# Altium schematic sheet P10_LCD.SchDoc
size A1
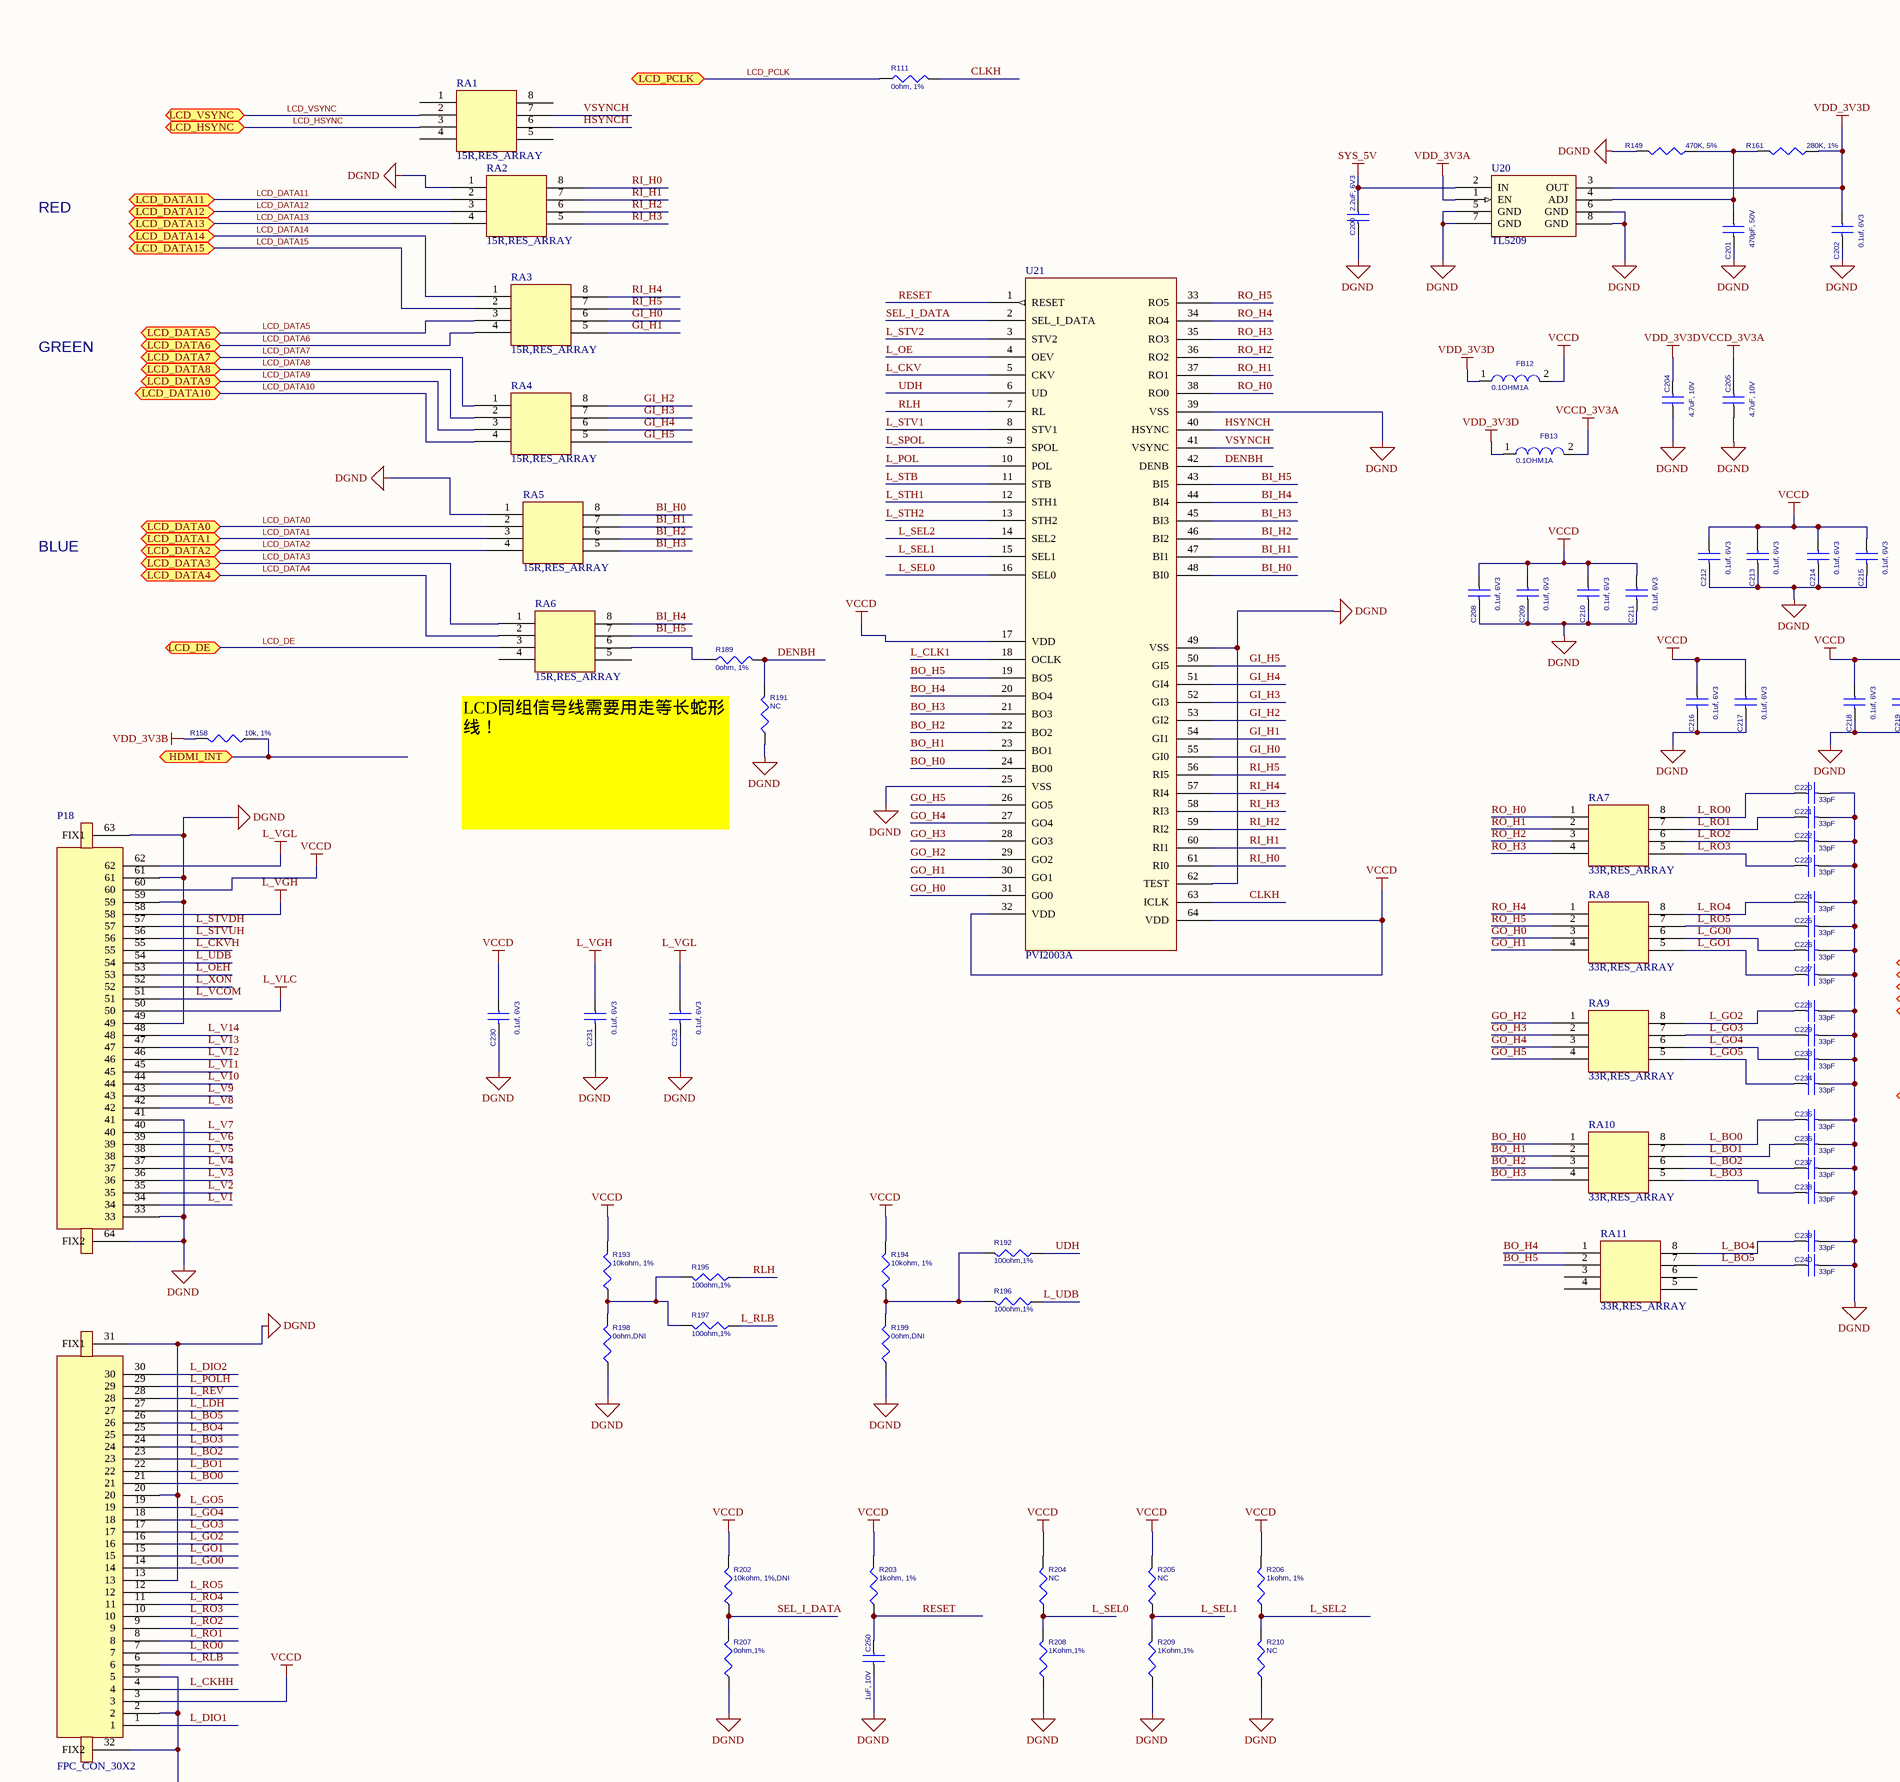
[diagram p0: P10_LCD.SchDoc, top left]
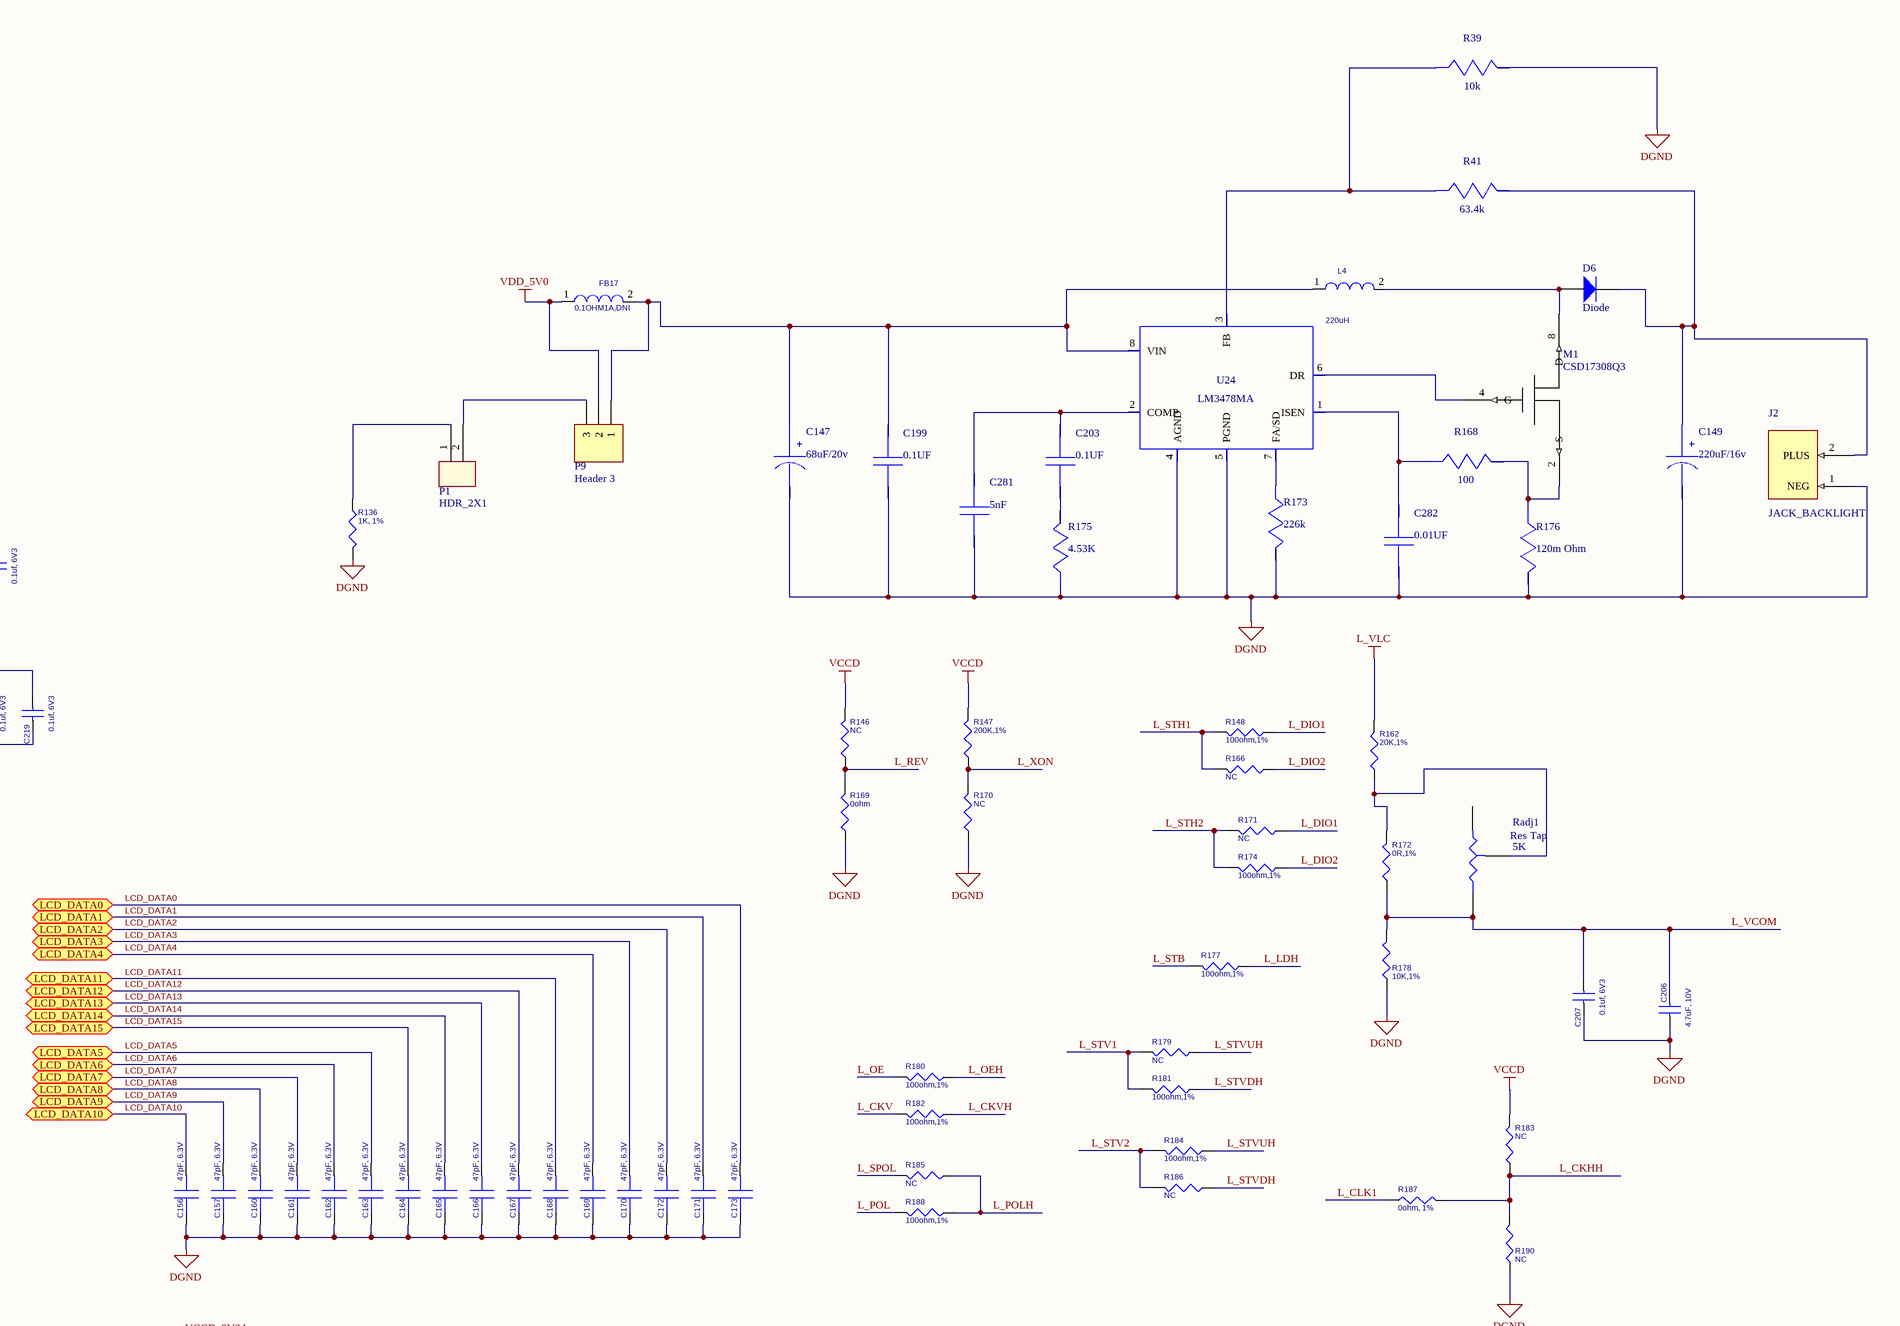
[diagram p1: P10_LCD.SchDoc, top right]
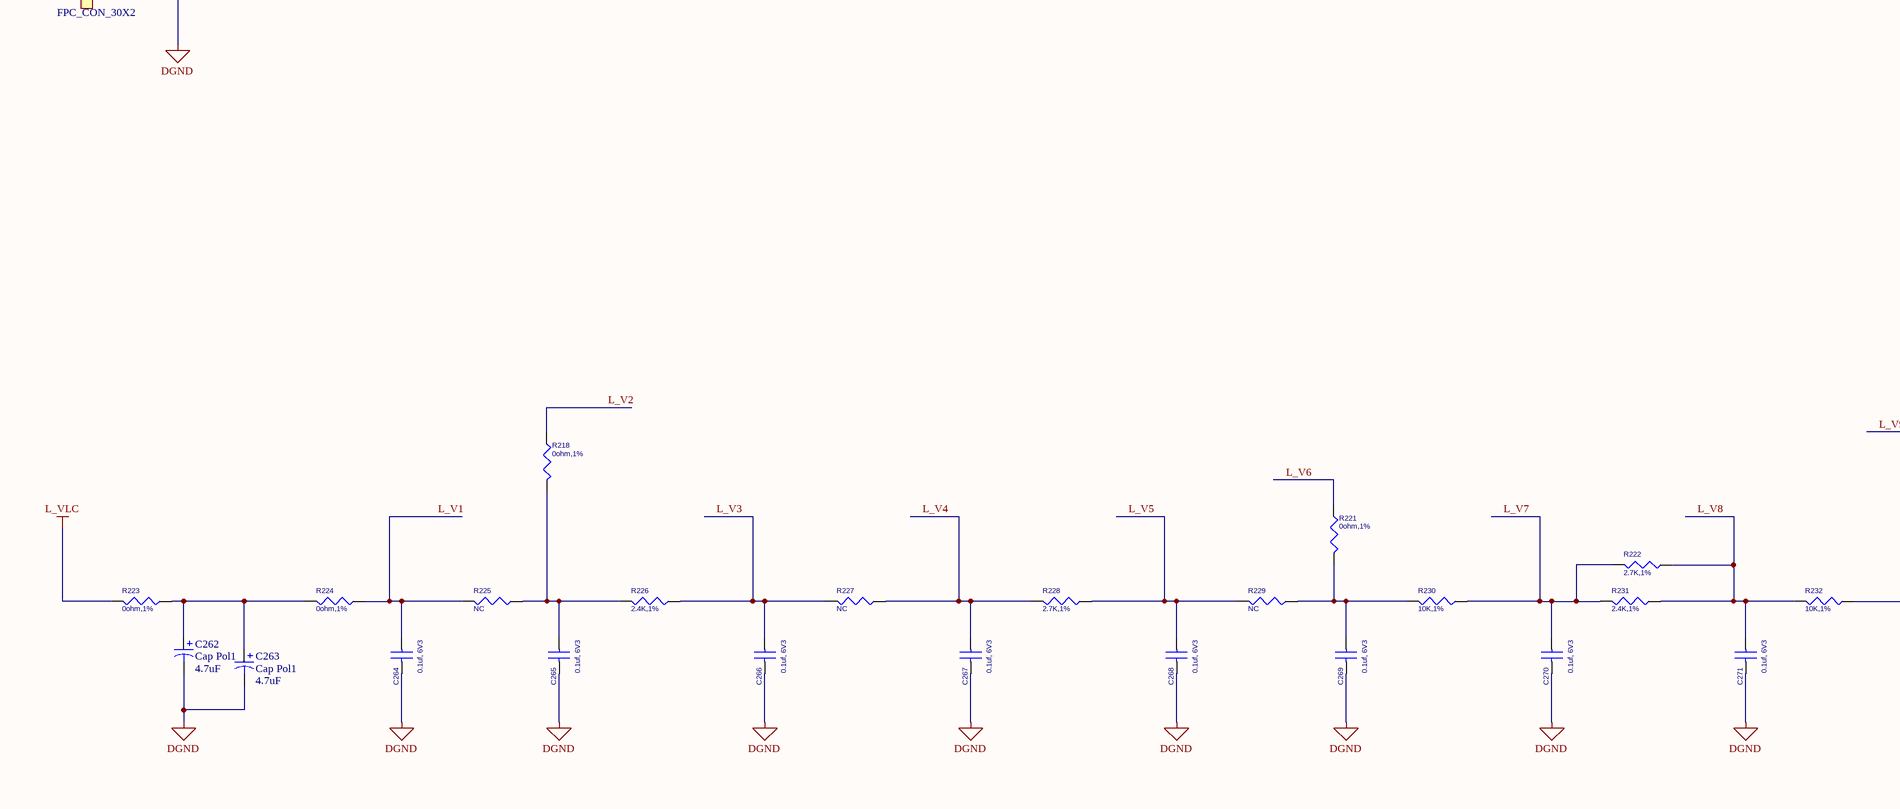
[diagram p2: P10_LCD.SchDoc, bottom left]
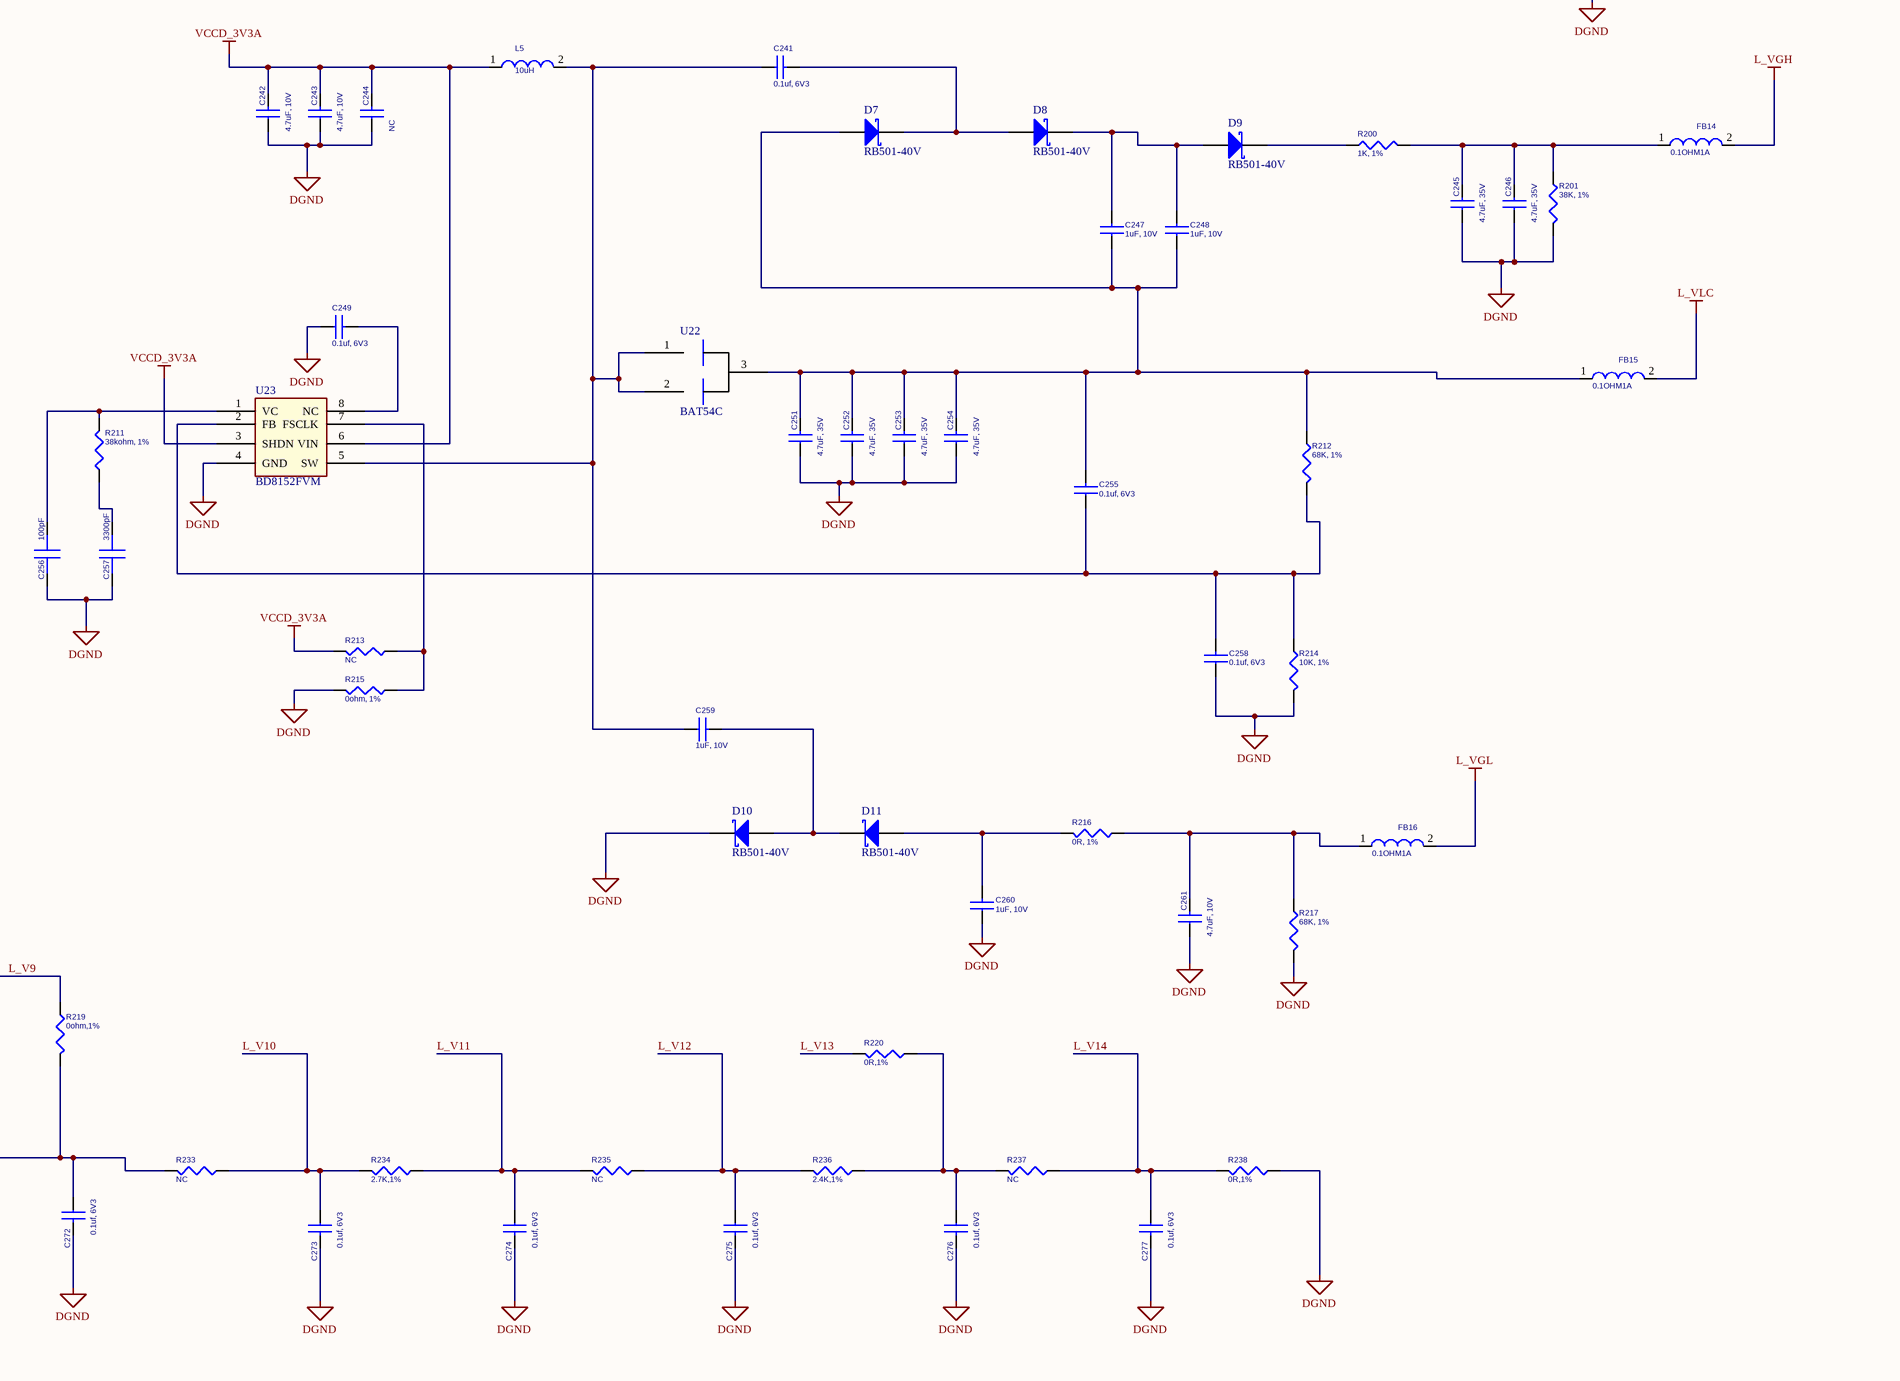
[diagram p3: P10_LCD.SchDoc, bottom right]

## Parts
C147  value 68uF/20v  [7343T]  (hidden comment: EEE-FK1A220R)
C149  value 220uF/16v  [7343T]  (hidden comment: 16SVP180M)
C156  47pF, 6.3V  [402]
C157  47pF, 6.3V  [402]
C160  47pF, 6.3V  [402]
C161  47pF, 6.3V  [402]
C162  47pF, 6.3V  [402]
C163  47pF, 6.3V  [402]
C164  47pF, 6.3V  [402]
C165  47pF, 6.3V  [402]
C166  47pF, 6.3V  [402]
C167  47pF, 6.3V  [402]
C168  47pF, 6.3V  [402]
C169  47pF, 6.3V  [402]
C170  47pF, 6.3V  [402]
C171  47pF, 6.3V  [402]
C172  47pF, 6.3V  [402]
C173  47pF, 6.3V  [402]
C199  value 0.1UF  [0805]  (hidden comment: C1005X5R0J104K)
C200  2.2uF, 6V3  [0805]
C201  470pF, 50V  [402]
C202  0.1uf, 6V3  [402]
C203  value 0.1UF  [0805]  (hidden comment: GRM216R71H103KA01D)
C204  4.7uF, 10V  [805]
C205  4.7uF, 10V  [805]
C206  4.7uF, 10V  [805]
C207  0.1uf, 6V3  [402]
C208  0.1uf, 6V3  [402]
C209  0.1uf, 6V3  [402]
C210  0.1uf, 6V3  [402]
C211  0.1uf, 6V3  [402]
C212  0.1uf, 6V3  [402]
C213  0.1uf, 6V3  [402]
C214  0.1uf, 6V3  [402]
C215  0.1uf, 6V3  [402]
C216  0.1uf, 6V3  [402]
C217  0.1uf, 6V3  [402]
C218  0.1uf, 6V3  [402]
C219  0.1uf, 6V3  [402]
C220  33pF  [402]
C221  33pF  [402]
C222  33pF  [402]
C223  33pF  [402]
C224  33pF  [402]
C225  33pF  [402]
C226  33pF  [402]
C227  33pF  [402]
C228  33pF  [402]
C229  33pF  [402]
C230  0.1uf, 6V3  [402]
C231  0.1uf, 6V3  [402]
C232  0.1uf, 6V3  [402]
C233  33pF  [402]
C234  33pF  [402]
C235  33pF  [402]
C236  33pF  [402]
C237  33pF  [402]
C238  33pF  [402]
C239  33pF  [402]
C240  33pF  [402]
C241  0.1uf, 6V3  [402]
C242  4.7uF, 10V  [805]
C243  4.7uF, 10V  [805]
C244  NC  [805]
C245  4.7uF, 35V  [1210]
C246  4.7uF, 35V  [1210]
C247  1uF, 10V  [0805]
C248  1uF, 10V  [0805]
C249  0.1uf, 6V3  [402]
C250  1uF, 10V  [0805]
C251  4.7uF, 35V  [1210]
C252  4.7uF, 35V  [1210]
C253  4.7uF, 35V  [1210]
C254  4.7uF, 35V  [1210]
C255  0.1uf, 6V3  [402]
C256  100pF  [402]
C257  3300pF  [C0603]
C258  0.1uf, 6V3  [402]
C259  1uF, 10V  [0805]
C260  1uF, 10V  [0805]
C261  4.7uF, 10V  [805]
C262  Cap Pol1  value 4.7uF  [6032/case C]
C263  Cap Pol1  value 4.7uF  [6032/case C]
C264  0.1uf, 6V3  [402]
C265  0.1uf, 6V3  [402]
C266  0.1uf, 6V3  [402]
C267  0.1uf, 6V3  [402]
C268  0.1uf, 6V3  [402]
C269  0.1uf, 6V3  [402]
C270  0.1uf, 6V3  [402]
C271  0.1uf, 6V3  [402]
C272  0.1uf, 6V3  [402]
C273  0.1uf, 6V3  [402]
C274  0.1uf, 6V3  [402]
C275  0.1uf, 6V3  [402]
C276  0.1uf, 6V3  [402]
C277  0.1uf, 6V3  [402]
C281  value 5nF  [0805]  (hidden comment: CC0805KRX7R9BB561)
C282  value 0.01UF  [0805]  (hidden comment: GRM216R71H103KA01D)
D6  Diode  [DSO-C2/X3.3]
D7  RB501-40V  [DSO-C2/X2.3]
D8  RB501-40V  [DSO-C2/X2.3]
D9  RB501-40V  [DSO-C2/X2.3]
D10  RB501-40V  [DSO-C2/X2.3]
D11  RB501-40V  [DSO-C2/X2.3]
FB12  0.1OHM1A  [SM-7351-IND-0805]
FB13  0.1OHM1A  [SM-7351-IND-0805]
FB14  0.1OHM1A  [SM-7351-IND-0805]
FB15  0.1OHM1A  [SM-7351-IND-0805]
FB16  0.1OHM1A  [SM-7351-IND-0805]
FB17  0.1OHM1A,DNI  [SM-7351-IND-0805]
J2  JACK_BACKLIGHT  [JACK_BACKLIGHT]
L4  220uH  [L330]
L5  10uH  [2520]
M1  CSD17308Q3  [MOSFET_Q3]
P1  HDR_2X1  [HDR_2X1]
P9  Header 3  [HDR1X3]
P18  FPC_CON_30X2  [FPC_CON_30X2]
R39  value 10k  [R0603]  (hidden comment: CRCW04021K00FKED)
R41  value 63.4k  [R0603]  (hidden comment: CRCW04027K68FKED)
R111  0ohm, 1%  [R0805]
R136  1K, 1%  [R0603]
R146  NC  [R0805]
R147  200K,1%  [R0805]
R148  100ohm,1%  [R0603]
R149  470K, 5%  [R0402]
R158  10k, 1%  [R0402]
R161  280K, 1%  [R0402]
R162  20K,1%  [R0805]
R166  NC  [R0603]
R168  value 100  [R0603]  (hidden comment: CRCW0402100RFKED)
R169  0ohm  [R0805]
R170  NC  [R0805]
R171  NC  [R0603]
R172  0R,1%  [R0805]
R173  value 226k  [R0603]  (hidden comment: CRCW040228K7FKED)
R174  100ohm,1%  [R0603]
R175  value 4.53K  [R0603]  (hidden comment: CRCW040211K0FKED)
R176  value 120m Ohm  [R2010]  (hidden comment: CSRN2010FK60L0)
R177  100ohm,1%  [R0603]
R178  10K,1%  [R0805]
R179  NC  [R0603]
R180  100ohm,1%  [R0603]
R181  100ohm,1%  [R0603]
R182  100ohm,1%  [R0603]
R183  NC  [R0805]
R184  100ohm,1%  [R0603]
R185  NC  [R0603]
R186  NC  [R0603]
R187  0ohm, 1%  [R0805]
R188  100ohm,1%  [R0603]
R189  0ohm, 1%  [R0805]
R190  NC  [R0805]
R191  NC  [R0805]
R192  100ohm,1%  [R0603]
R193  10kohm, 1%  [R0805]
R194  10kohm, 1%  [R0805]
R195  100ohm,1%  [R0603]
R196  100ohm,1%  [R0603]
R197  100ohm,1%  [R0603]
R198  0ohm,DNI  [R0805]
R199  0ohm,DNI  [R0805]
R200  1K, 1%  [R0805]
R201  38K, 1%  [R0805]
R202  10kohm, 1%,DNI  [R0805]
R203  1kohm, 1%  [R0805]
R204  NC  [R0805]
R205  NC  [R0805]
R206  1kohm, 1%  [R0805]
R207  0ohm,1%  [R0805]
R208  1Kohm,1%  [R0805]
R209  1Kohm,1%  [R0805]
R210  NC  [R0805]
R211  38kohm, 1%  [R0805]
R212  68K, 1%  [R0805]
R213  NC  [R0805]
R214  10K, 1%  [R0805]
R215  0ohm, 1%  [R0805]
R216  0R, 1%  [R0805]
R217  68K, 1%  [R0805]
R218  0ohm,1%  [R0805]
R219  0ohm,1%  [R0805]
R220  0R,1%  [R0805]
R221  0ohm,1%  [R0805]
R222  2.7K,1%  [R0805]
R223  0ohm,1%  [R0805]
R224  0ohm,1%  [R0805]
R225  NC  [R0805]
R226  2.4K,1%  [R0805]
R227  NC  [R0805]
R228  2.7K,1%  [R0805]
R229  NC  [R0805]
R230  10K,1%  [R0805]
R231  2.4K,1%  [R0805]
R232  10K,1%  [R0805]
R233  NC  [R0805]
R234  2.7K,1%  [R0805]
R235  NC  [R0805]
R236  2.4K,1%  [R0805]
R237  NC  [R0805]
R238  0R,1%  [R0805]
RA1  15R,RES_ARRAY  [R8_0603]
RA2  15R,RES_ARRAY  [R8_0603]
RA3  15R,RES_ARRAY  [R8_0603]
RA4  15R,RES_ARRAY  [R8_0603]
RA5  15R,RES_ARRAY  [R8_0603]
RA6  15R,RES_ARRAY  [R8_0603]
RA7  33R,RES_ARRAY  [R8_0603]
RA8  33R,RES_ARRAY  [R8_0603]
RA9  33R,RES_ARRAY  [R8_0603]
RA10  33R,RES_ARRAY  [R8_0603]
RA11  33R,RES_ARRAY  [R8_0603]
Radj1  Res Tap  value 5K  [RADJ]
U20  TL5209  [SO8-25X75/TL5209DR/8-SOIC]
U21  PVI2003A  [TQFP13-64 STD/PVI2003A]
U22  BAT54C  [SOT-23/BAT54C]
U23  BD8152FVM  [MSOP8/BD8152FVM]
U24  LM3478MA  [SOP8_LM3478]

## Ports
HDMI_INT, LCD_DATA0, LCD_DATA1, LCD_DATA2, LCD_DATA3, LCD_DATA4, LCD_DATA5, LCD_DATA6, LCD_DATA7, LCD_DATA8, LCD_DATA9, LCD_DATA10, LCD_DATA11, LCD_DATA12, LCD_DATA13, LCD_DATA14, LCD_DATA15, LCD_DE, LCD_HSYNC, LCD_PCLK, LCD_VSYNC

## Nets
DGND: C147.2(-) C149.2(-) C156.2 C157.2 C160.2 C161.2 C162.2 C163.2 C164.2 C165.2 C166.2 C167.2 C168.2 C169.2 C170.2 C171.2 C172.2 C173.2 C199.2 C200.2 C201.2 C202.2 C204.1 C205.1 C206.1 C207.2 C208.2 C209.2 C210.2 C211.2 C212.2 C213.2 C214.2 C215.2 C216.2 C217.2 C218.2 C219.2 C220.2 C221.2 C222.2 C223.2 C224.2 C225.2 C226.2 C227.2 C228.2 C229.2 C230.2 C231.2 C232.2 C233.2 C234.2 C235.2 C236.2 C237.2 C238.2 C239.2 C240.2 C242.1 C243.1 C244.1 C245.1 C246.1 C249.1 C250.2 C251.1 C252.1 C253.1 C254.1 C256.2 C257.2 C258.1 C260.1 C261.1 C262.2 C263.2 C264.2 C265.2 C266.2 C267.2 C268.2 C269.2 C270.2 C271.2 C272.2 C273.2 C274.2 C275.2 C276.2 C277.2 C281.2 C282.2 D10.2(K) J2.1(NEG) P18.2 P18.5 P18.13 P18.20 P18.31(FIX1) P18.32(FIX2) P18.33 P18.41 P18.49 P18.59 P18.61 P18.63(FIX1) P18.64(FIX2) R39.1 R136.2 R149.2 R169.2(P2) R170.2(P2) R173.1 R175.2 R176.1 R178.2(P2) R190.2(P2) R191.2(P2) R198.2(P2) R199.2(P2) R201.1(P1) R207.2(P2) R208.2(P2) R209.2(P2) R210.2(P2) R214.1(P1) R215.1(P1) R217.1(P1) R238.2(P2) RA2.1 RA5.1 U20.5(GND) U20.6(GND) U20.7(GND) U20.8(GND) U21.25(VSS) U21.39(VSS) U21.49(VSS) U21.62(TEST) U23.4(GND) U24.4(AGND) U24.5(PGND)
L_VGH: C231.1 FB14.2 P18.58
L_VGL: C232.1 FB16.2 P18.62
L_VLC: FB15.2 P18.50 R162.1(P1) R223.1(P1)
SYS_5V: C200.1 U20.2(IN)
VCCD: C208.1 C209.1 C210.1 C211.1 C212.1 C213.1 C214.1 C215.1 C216.1 C217.1 C218.1 C219.1 C230.1 FB12.2 P18.3 P18.60 R146.1(P1) R147.1(P1) R183.1(P1) R193.1(P1) R194.1(P1) R202.1(P1) R203.1(P1) R204.1(P1) R205.1(P1) R206.1(P1) U21.17(VDD) U21.32(VDD) U21.64(VDD)
VCCD_3V3A: C205.2 C242.2 C243.2 C244.2 FB13.2 L5.1 R213.1(P1) U23.3(SHDN) U23.6(VIN)
VDD_3V3A: U20.1(EN)
VDD_3V3B: R158.1(P1)
VDD_3V3D: C202.1 C204.2 FB12.1 FB13.1 R161.1 U20.3(OUT)
VDD_5V0: FB17.1 P9.2
BI_H0: RA5.8 U21.48(BI0)
BI_H1: RA5.7 U21.47(BI1)
BI_H2: RA5.6 U21.46(BI2)
BI_H3: RA5.5 U21.45(BI3)
BI_H4: RA6.8 U21.44(BI4)
BI_H5: RA6.7 U21.43(BI5)
BO_H0: RA10.1 U21.24(BO0)
BO_H1: RA10.2 U21.23(BO1)
BO_H2: RA10.3 U21.22(BO2)
BO_H3: RA10.4 U21.21(BO3)
BO_H4: RA11.1 U21.20(BO4)
BO_H5: RA11.2 U21.19(BO5)
CLKH: R111.1(P1) U21.63(ICLK)
DENBH: R189.1(P1) R191.1(P1) U21.42(DENB)
GI_H0: RA3.6 U21.55(GI0)
GI_H1: RA3.5 U21.54(GI1)
GI_H2: RA4.8 U21.53(GI2)
GI_H3: RA4.7 U21.52(GI3)
GI_H4: RA4.6 U21.51(GI4)
GI_H5: RA4.5 U21.50(GI5)
GO_H0: RA8.3 U21.31(GO0)
GO_H1: RA8.4 U21.30(GO1)
GO_H2: RA9.1 U21.29(GO2)
GO_H3: RA9.2 U21.28(GO3)
GO_H4: RA9.3 U21.27(GO4)
GO_H5: RA9.4 U21.26(GO5)
HDMI_INT: R158.2(P2) ; port HDMI_INT
HSYNCH: RA1.6 U21.40(HSYNC)
L_BO0: C235.1 P18.21 RA10.8
L_BO1: C236.1 P18.22 RA10.7
L_BO2: C237.1 P18.23 RA10.6
L_BO3: C238.1 P18.24 RA10.5
L_BO4: C239.1 P18.25 RA11.8
L_BO5: C240.1 P18.26 RA11.7
L_CKHH: P18.4 R183.2(P2) R187.1(P1) R190.1(P1)
L_CKV: R182.1(P1) U21.5(CKV)
L_CKVH: P18.55 R182.2(P2)
L_CLK1: R187.2(P2) U21.18(OCLK)
L_DIO1: P18.1 R148.2(P2) R171.2(P2)
L_DIO2: P18.30 R166.2(P2) R174.2(P2)
L_GO0: C226.1 P18.14 RA8.6
L_GO1: C227.1 P18.15 RA8.5
L_GO2: C228.1 P18.16 RA9.8
L_GO3: C229.1 P18.17 RA9.7
L_GO4: C233.1 P18.18 RA9.6
L_GO5: C234.1 P18.19 RA9.5
L_LDH: P18.27 R177.2(P2)
L_OE: R180.1(P1) U21.4(OEV)
L_OEH: P18.53 R180.2(P2)
L_POL: R188.1(P1) U21.10(POL)
L_POLH: P18.29 R185.2(P2) R188.2(P2)
L_REV: P18.28 R146.2(P2) R169.1(P1)
L_RLB: P18.6 R197.2(P2)
L_RO0: C220.1 P18.7 RA7.8
L_RO1: C221.1 P18.8 RA7.7
L_RO2: C222.1 P18.9 RA7.6
L_RO3: C223.1 P18.10 RA7.5
L_RO4: C224.1 P18.11 RA8.8
L_RO5: C225.1 P18.12 RA8.7
L_SEL0: R204.2(P2) R208.1(P1) U21.16(SEL0)
L_SEL1: R205.2(P2) R209.1(P1) U21.15(SEL1)
L_SEL2: R206.2(P2) R210.1(P1) U21.14(SEL2)
L_SPOL: R185.1(P1) U21.9(SPOL)
L_STB: R177.1(P1) U21.11(STB)
L_STH1: R148.1(P1) R166.1(P1) U21.12(STH1)
L_STH2: R171.1(P1) R174.1(P1) U21.13(STH2)
L_STV1: R179.1(P1) R181.1(P1) U21.8(STV1)
L_STV2: R184.1(P1) R186.1(P1) U21.3(STV2)
L_STVDH: P18.57 R181.2(P2) R186.2(P2)
L_STVUH: P18.56 R179.2(P2) R184.2(P2)
L_UDB: P18.54 R196.2(P2)
L_V1: C264.1 P18.34 R224.2(P2) R225.1(P1)
L_V2: P18.35 R218.2(P2)
L_V3: C266.1 P18.36 R226.2(P2) R227.1(P1)
L_V4: C267.1 P18.37 R227.2(P2) R228.1(P1)
L_V5: C268.1 P18.38 R228.2(P2) R229.1(P1)
L_V6: P18.39 R221.2(P2)
L_V7: C270.1 P18.40 R222.1(P1) R230.2(P2) R231.1(P1)
L_V8: C271.1 P18.42 R222.2(P2) R231.2(P2) R232.1(P1)
L_V9: P18.43 R219.2(P2)
L_V10: C273.1 P18.44 R233.2(P2) R234.1(P1)
L_V11: C274.1 P18.45 R234.2(P2) R235.1(P1)
L_V12: C275.1 P18.46 R235.2(P2) R236.1(P1)
L_V13: P18.47 R220.1(P1)
L_V14: C277.1 P18.48 R237.2(P2) R238.1(P1)
L_VCOM: C206.2 C207.1 P18.51 R172.2(P2) R178.1(P1) Radj1.2(B)
L_XON: P18.52 R147.2(P2) R170.1(P1)
LCD_DATA0: C173.1 RA5.2 ; port LCD_DATA0
LCD_DATA1: C171.1 RA5.3 ; port LCD_DATA1
LCD_DATA2: C172.1 RA5.4 ; port LCD_DATA2
LCD_DATA3: C170.1 RA6.1 ; port LCD_DATA3
LCD_DATA4: C169.1 RA6.2 ; port LCD_DATA4
LCD_DATA5: C163.1 RA3.3 ; port LCD_DATA5
LCD_DATA6: C162.1 RA3.4 ; port LCD_DATA6
LCD_DATA7: C161.1 RA4.1 ; port LCD_DATA7
LCD_DATA8: C160.1 RA4.2 ; port LCD_DATA8
LCD_DATA9: C157.1 RA4.3 ; port LCD_DATA9
LCD_DATA10: C156.1 RA4.4 ; port LCD_DATA10
LCD_DATA11: C168.1 RA2.2 ; port LCD_DATA11
LCD_DATA12: C167.1 RA2.3 ; port LCD_DATA12
LCD_DATA13: C166.1 RA2.4 ; port LCD_DATA13
LCD_DATA14: C165.1 RA3.1 ; port LCD_DATA14
LCD_DATA15: C164.1 RA3.2 ; port LCD_DATA15
LCD_DE: RA6.3 ; port LCD_DE
LCD_HSYNC: RA1.3 ; port LCD_HSYNC
LCD_PCLK: R111.2(P2) ; port LCD_PCLK
LCD_VSYNC: RA1.2 ; port LCD_VSYNC
RESET: C250.1 R203.2(P2) U21.1(RESET)
RI_H0: RA2.8 U21.61(RI0)
RI_H1: RA2.7 U21.60(RI1)
RI_H2: RA2.6 U21.59(RI2)
RI_H3: RA2.5 U21.58(RI3)
RI_H4: RA3.8 U21.57(RI4)
RI_H5: RA3.7 U21.56(RI5)
RLH: R195.2(P2) U21.7(RL)
RO_H0: RA7.1 U21.38(RO0)
RO_H1: RA7.2 U21.37(RO1)
RO_H2: RA7.3 U21.36(RO2)
RO_H3: RA7.4 U21.35(RO3)
RO_H4: RA8.1 U21.34(RO4)
RO_H5: RA8.2 U21.33(RO5)
SEL_I_DATA: R202.2(P2) R207.1(P1) U21.2(SEL_I_DATA)
UDH: R192.2(P2) U21.6(UD)
VSYNCH: RA1.7 U21.41(VSYNC)
NetC147_1: C147.1(+) C199.1 FB17.2 L4.1 P9.1 U24.8(VIN)
NetC149_1: C149.1(+) D6.2(K) J2.2(PLUS) R41.1
NetC201_1: C201.1 R149.1 R161.2 U20.4(ADJ)
NetC203_1: C203.1 C281.1 U24.2(COMP)
NetC203_2: C203.2 R175.1
NetC241_1: C241.1 C259.1 L5.2 U22.1 U22.2 U23.5(SW)
NetC241_2: C241.2 D7.2(K) D8.1(A)
NetC245_2: C245.2 C246.2 FB14.1 R200.1(P1) R201.2(P2)
NetC247_1: C247.1 C248.1 C251.2 C252.2 C253.2 C254.2 C255.2 D7.1(A) FB15.1 R212.2(P2) U22.3
NetC247_2: C247.2 C248.2 D8.2(K) D9.1(A)
NetC249_2: C249.2 U23.8(NC)
NetC255_1: C255.1 C258.2 R212.1(P1) R214.2(P2) U23.2(FB)
NetC256_1: C256.1 R211.1(P1) U23.1(VC)
NetC257_1: C257.1 R211.2(P2)
NetC259_2: C259.2 D10.1(A) D11.2(K)
NetC260_2: C260.2 D11.1(A) R216.1(P1)
NetC261_2: C261.2 FB16.1 R216.2(P2) R217.2(P2)
NetC262_1: C262.1 C263.1 R223.2(P2) R224.1(P1)
NetC265_1: C265.1 R218.1(P1) R225.2(P2) R226.1(P1)
NetC269_1: C269.1 R221.1(P1) R229.2(P2) R230.1(P1)
NetC272_1: C272.1 R219.1(P1) R232.2(P2) R233.1(P1)
NetC276_1: C276.1 R220.2(P2) R236.2(P2) R237.1(P1)
NetC282_1: C282.1 R168.2 U24.1(ISEN)
NetD6_1: D6.1(A) L4.2 M1.8(D)
NetD9_2: D9.2(K) R200.2(P2)
NetM1_2: M1.2(S) R168.1 R176.2
NetM1_4: M1.4(G) U24.6(DR)
NetP1_1: P1.1 R136.1
NetP1_2: P1.2 P9.3
NetR39_2: R39.2 R41.2 U24.3(FB)
NetR162_2: R162.2(P2) R172.1(P1) Radj1.3(TAP)
NetR173_2: R173.2 U24.7(FA/SD)
NetR189_2: R189.2(P2) RA6.6
NetR192_1: R192.1(P1) R194.2(P2) R196.1(P1) R199.1(P1)
NetR193_2: R193.2(P2) R195.1(P1) R197.1(P1) R198.1(P1)
NetR213_2: R213.2(P2) R215.2(P2) U23.7(FSCLK)

Not connected (* = marked no-connect by the designer): RA1 1 4 5 8; RA6 4 5; RA11 3 4 5 6; Radj1 1(A)

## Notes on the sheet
- RED
- GREEN
- BLUE
- LCD同组信号线需要用走等长蛇形线！

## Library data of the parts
C147 = EEE-FK1A220R: Manufacturer Name: Panasonic
C149 = 16SVP180M: Manufacturer Name: Sanyo
C156 C157 C160-C173 C256 C257 = CAP SMD: CAP CER 47PF 50V 5% NP0 0402; Manufacturer: TDK Corporation; Manufacturer Part Number: C1005C0G1H470J050BA; Tolerance: ?%; Temperature Coefficient: C0G, NP0
C199 = C1005X5R0J104K: Manufacturer Name: TDK
C200 = CAP_2.2uF_X5R_6.3V_10%_0402: CAP CER 2.2UF 6.3V 10% X5R 0402; Manufacturer: TDK Corporation; Manufacturer Part Number: C1005X5R0J225K050BC; Capacitance: 2.2µF; Tolerance: ?0%
C201 C220-C229 C233-C240 = CAP_2.2uF_X5R_6.3V_10%_0402: CAP CER 470PF 50V 10% X7R 0402; Manufacturer: Murata Electronics North America; Manufacturer Part Number: GRM155R71H471KA01D; Tolerance: ?0%
C202 C207-C219 C230-C232 C241 C249 C255 C258 C264-C277 = CAP_0.1uF_X7R_16V_10% 0402: CAP CER 0.1UF 6.3V 10% X5R 0402; Manufacturer: TDK Corporation; Manufacturer Part Number: C1005X5R0J104K050BA; Capacitance: 0.1µF; Tolerance: ?0%
C203 C282 = GRM216R71H103KA01D: GRM216R71H103KA0; Manufacturer Name: MuRata
C204-C206 C242-C246 C251-C254 C261 = CAP_10uF_Y5V_10V_10%_0805: CAP CER 10UF 10V Y5V 0805; Manufacturer: TDK Corporation; Manufacturer Part Number: C2012Y5V1A106Z; Capacitance: 10µF; Tolerance: -20%, +80%; Temperature Coefficient: Y5V (F)
C247 C248 C250 C259 C260 = CAP_1.0UF_X5R_10V_10%_0402: CAP CER 1UF 10V 10% X5R 0402; Manufacturer: AVX Corporation; Manufacturer Part Number: 0402ZD105KAT2A; Capacitance: 1.0µF; Tolerance: ?0%
C262 C263 = Cap Pol1: Polarized Capacitor (Radial)
C281 = CC0805KRX7R9BB561: CC0805KRX7R9BB56; Manufacturer Name: Yageo America
D6 = Diode: Default Diode
D7-D11 = D Schottky: Schottky Diode
FB12-FB17 = FER_180_200_0: FERRITE 800MA 150 OHM 0805 SMD; PartName: FerriteBead150ohm800mA; Mfr: Steward; MfrNum: LI0805H151R-10; TIIntPartnumber: 1L0010; Manufacturer: Laird-Signal Integrity Products; Vendor: Digikey; Impedance @ Frequency: 150 Ohm @ 100MHz; DC Resistance (DCR): 150 mOhm Max; Filter Type: Differential Mode - Single
L4 L5 = IND_2.2uH_2.6A_10%_SMD: INDUCTOR 2.2UH 20% 1300MA 1008; PartName: 2.2uH10%2.6Asmd; Mfr: TDK; MfrNum: VLCF5020T-2R2N2R6-3; TIIntPartnumber: 1L0025; Manufacturer: Murata Electronics North America; Manufacturer Part Number: LQM2HPN2R2MG0L; Vendor: Digikey; Cost100: 1.11; Cost10K: 0.37; Inductance: 2.2µH; Current Rating: 1.3A; Tolerance: ?0%; Shielding: Shielded; DC Resistance (DCR): 100 mOhm Max; Frequency - Self Resonant: 40MHz; Frequency - Test: 1MHz
M1 = M2_X
P9 = Header 3: Header, 3-Pin
R39 = CRCW04021K00FKED: Manufacturer Name: Vishay-Dale
R41 = CRCW04027K68FKED: Manufacturer Name: Vishay-Dale
R111 R146-R148 R158 R162 R166 R169-R172 R174 R177-R238 = RES SMD: RES 10K OHM 1/16W 5% 0402 SMD; Manufacturer: Rohm Semiconductor; Manufacturer Part Number: MCR01MZPJ103; Power (Watts): 0.063W, 1/16W; Temperature Coefficient: ?00ppm/°C; Tolerance: ?%
R136 = RES_0_1/16W_1%_0402: RES 0.0 OHM,0603,DNI; Manufacturer: Yageo; Manufacturer Part Number: RC0402JR-070RL; Resistance (Ohms): 0.0; Power (Watts): 0.063W, 1/16W; Tolerance: Jumper
R149 = RES_470_1/10W_5%_0402: RES 470K OHM 1/16W 1% 0402 SMD; Manufacturer: Yageo; Manufacturer Part Number: RC0402FR-07470KL; Power (Watts): 0.063W, 1/16W; Temperature Coefficient: ?00ppm/°C; Tolerance: ?%
R161 = RES_470_1/10W_5%_0402: RES 280K OHM 1/16W 1% 0402 SMD; Manufacturer: Stackpole Electronics Inc; Manufacturer Part Number: RMCF0402FT280K; Power (Watts): 0.063W, 1/16W; Temperature Coefficient: ?00ppm/°C; Tolerance: ?%
R168 = CRCW0402100RFKED: Manufacturer Name: Vishay-Dale
R173 = CRCW040228K7FKED: Manufacturer Name: Vishay-Dale
R175 = CRCW040211K0FKED: Manufacturer Name: Vishay-Dale
R176 = CSRN2010FK60L0: Manufacturer Name: Stackpole Electronics Inc
RA1-RA11 = RES_ARRAY
Radj1 = Res Tap: Tapped Resistor; Sim Note: Enter the Resistance value and the set point into parameter fields.; Set Position: 0.5
U20 = TL5209: IC LDO VOLT REG 500MA 8-SOIC; Manufacturer: Texas Instruments; Manufacturer Part Number: TL5209DR; Regulator Topology: Positive Adjustable; Voltage - Output: 2.5 V ~ 6.5 V; Voltage - Input: 2.5 V ~ 16 V; Voltage - Dropout (Typical): 0.35V @ 500mA; Number of Regulators: 1; Current - Output: 500mA (Max)
U24 = LM3478MM/NOPB: Manufacturer Name: Texas Instruments; Value: UNLISTED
